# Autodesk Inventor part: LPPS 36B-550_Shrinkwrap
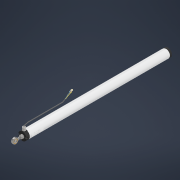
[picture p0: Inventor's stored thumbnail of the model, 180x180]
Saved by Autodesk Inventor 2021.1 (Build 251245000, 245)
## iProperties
Created: 2020-09
Part Number: LPPS 36B-550_Shrinkwrap
Material: Generic
Document SubType Name: Modeling
Designer: J. Nielson
Density: 1 g/cm^3
Appearance: Default
Author: J. Nielson
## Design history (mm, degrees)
derived "LPPS 36B-550.iam"
body "Solid1"
node "LPPS 36B Cable End Cap.iam:1::LPPS-36B PLASTIC CABLE END.ipt"
node "LPPS 36B Cable End Cap.iam:1::LPPS 36B- Cable Gland.ipt:1"
body "Solid2"
node "LPPS 36B Cable End Cap.iam:1::Cable Gland Cap.ipt:1"
body "Solid3"
node "LPPS 36B Cable End Cap.iam:1::Cable.ipt:1"
body "Solid4"
node "LPPS 36B Cable End Cap.iam:1::Cable Gland Seal 1 of 2.ipt:1"
body "Solid5"
node "LPPS 36B Cable End Cap.iam:1::Cable Gland 2 of 2.ipt:1"
body "Solid6"
node "LPPS 36B Cable End Cap.iam:1::#6 Terminal Ring 22 - 18 AWG.i"
body "Solid7"
node "LPPS-36B-550 METAL HOUSING.ipt:1"
body "Solid8"
node "MALE Rod Eye SW.ipt:1"
body "Solid9"
node "LPPS-36B PLASTIC STROKE END.ipt:1"
body "Solid10"
node "LPPS-36B-550 Back Stop.ipt:1"
body "Solid11"
node "LPPS-36B-550 Front Stop.ipt:1"
body "Solid12"
node "AS 1427 - M3 x 16.ipt:1"
body "Solid13"
node "AS 1427 - M3 x 16.ipt:2"
body "Solid14"
node "AS 1427 - M3 x 16.ipt:3"
body "Solid15"
node "AS 1427 - M3 x 16.ipt:4"
body "Solid16"
node "AS 1112 - M8  Type 5.ipt:1"
body "Solid17"
node "AS 1237 - 8.ipt:1"
body "Solid18"
node "AS 1968 - 1976 - 8.ipt:1"
body "Solid19"
